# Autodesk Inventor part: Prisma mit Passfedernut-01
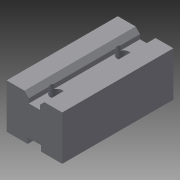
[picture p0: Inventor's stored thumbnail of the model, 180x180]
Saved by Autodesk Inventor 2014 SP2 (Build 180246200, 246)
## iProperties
Created: 2015-06
Part Number: Prisma mit Passfedernut-01
Material: Generisch
Document SubType Name: Modeling
Designer: e_krauts
Density: 1 g/cm^3
Appearance: Vorgabe
Author: e_krauts
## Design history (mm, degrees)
sketch "Skizze2"
  geometry: L1 (-12.5, 0)-(12.5, 0) reference; L2 (-12.5, 20)-(-12.5, 0) reference; L3 (0, 7)-(0, -1.145) reference; L4 (-3, 0)-(-3, 2.5); L5 (-3, 2.5)-(3, 2.5); L6 (3, 2.5)-(3, 0); 1 further point
  constraints: 8 end point, 2 parallel, 2 perpendicular, 2 point on line, 1 vertical, 1 other
  dimensions: "d17" = 6 distance between parallel lines of L6 L4; "d18" = 2.5 distance between parallel lines of L1 L5
extrude "Extrusion1" new body sketch "Skizze2" stored distance "d13" = 50; taper "d14" = 0 deg
extrude "Extrusion2" cut sketch "Skizze2" stored distance "d19" = 50; taper "d20" = 0 deg
sketch "Skizze4"
  geometry: L1 (8, -50)-(0, -50) reference; L2 (-4.5, 3)-(-4.5, -65); L3 (-22, -25)-(16, -25) reference; 3 further points
  constraints: 4 end point, 2 perpendicular, 2 point on line, 1 horizontal, 1 symmetric about line
  dimensions: "d21" = 30 distance of point (-4.5, -40) point (-4.5, -10)
hole "Bohrung1" sketch "Skizze4" at (-4.5, -10), (-4.5, -40) diameter "d22" = 2.9; stored, may be unused: countersink angle "d26" = 90 deg, drill point angle "d28" = 118 deg; dims "d23" = 6, "d24" = 5.5, "d25" = 10, "d27" = 8
sketch "Skizze5"
  geometry: L1 (-12.5, 0)-(12.5, 0) reference; L2 (-12.5, 20)-(-12.5, 0) reference; L3 (0, 3.75)-(0, -3) reference; L4 (-4, 0)-(-4, -2.25); L5 (-4, -2.25)-(4, -2.25); L6 (4, -2.25)-(4, 0); 1 further point
  constraints: 8 end point, 3 parallel, 2 point on line, 1 perpendicular, 1 vertical, 1 other
  dimensions: "d29" = 8 distance between parallel lines of L6 L4; "d30" = 2.25 distance between parallel lines of L1 L5
extrude "Extrusion3" join sketch "Skizze5" stored distance "d31" = 10; taper "d32" = 0 deg
sketch "Skizze6"
  geometry: L1 (8, -50)-(0, -50) reference; L2 (10, -27.5)-(-19.574, -27.5); 2 further points
  constraints: 2 end point, 1 coincident, 1 parallel
hole "Bohrung2" sketch "Skizze6" at (-4.5, -25) diameter "d33" = 2.9; stored, may be unused: countersink angle "d37" = 90 deg, drill point angle "d39" = 118 deg; dims "d34" = 6, "d35" = 5.5, "d36" = 10, "d38" = 8
node "Volumenkörper1"
sketch "Skizze1"
  geometry: L1 (0, 0)-(0, 56) reference; L2 (0, 0)-(-12.5, 0); L3 (-12.5, 0)-(-12.5, 20); L4 (-12.5, 20)-(-4.5, 20); L5 (-4.5, 20)-(-2.5, 18); L6 (-2.5, 18)-(-2.5, 16); L7 (-2.5, 16)-(0, 16); L8 (0, 0)-(12.5, 0); L9 (12.5, 0)-(12.5, 20); L10 (12.5, 20)-(4.5, 20); L11 (4.5, 20)-(2.5, 18); L12 (2.5, 18)-(2.5, 16); L13 (2.5, 16)-(0, 16)
  constraints: 26 end point, 5 symmetric about line, 3 perpendicular, 2 parallel, 2 vertical, 1 point on line
  dimensions: "d7" = 5 diameter of L6 L1; "d8" = 4 distance between parallel lines of L7 L4; "d9" = 2 distance from line of L7 L5.end; "d10" = 45 deg angle of L1 L5; "d11" = 25 diameter of L3 L1; "d12" = 20 distance between parallel lines of L2 L4
